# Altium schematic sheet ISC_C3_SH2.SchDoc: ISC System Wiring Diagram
size C; DrawnBy: Filiberto Clara; Engineer: Filiberto Clara; Organization: LIGO Laboratory; Address1: California Institute of Technology; Address2: Massachusetts Institute of Technology; SheetNumber: 6; SheetTotal: 37
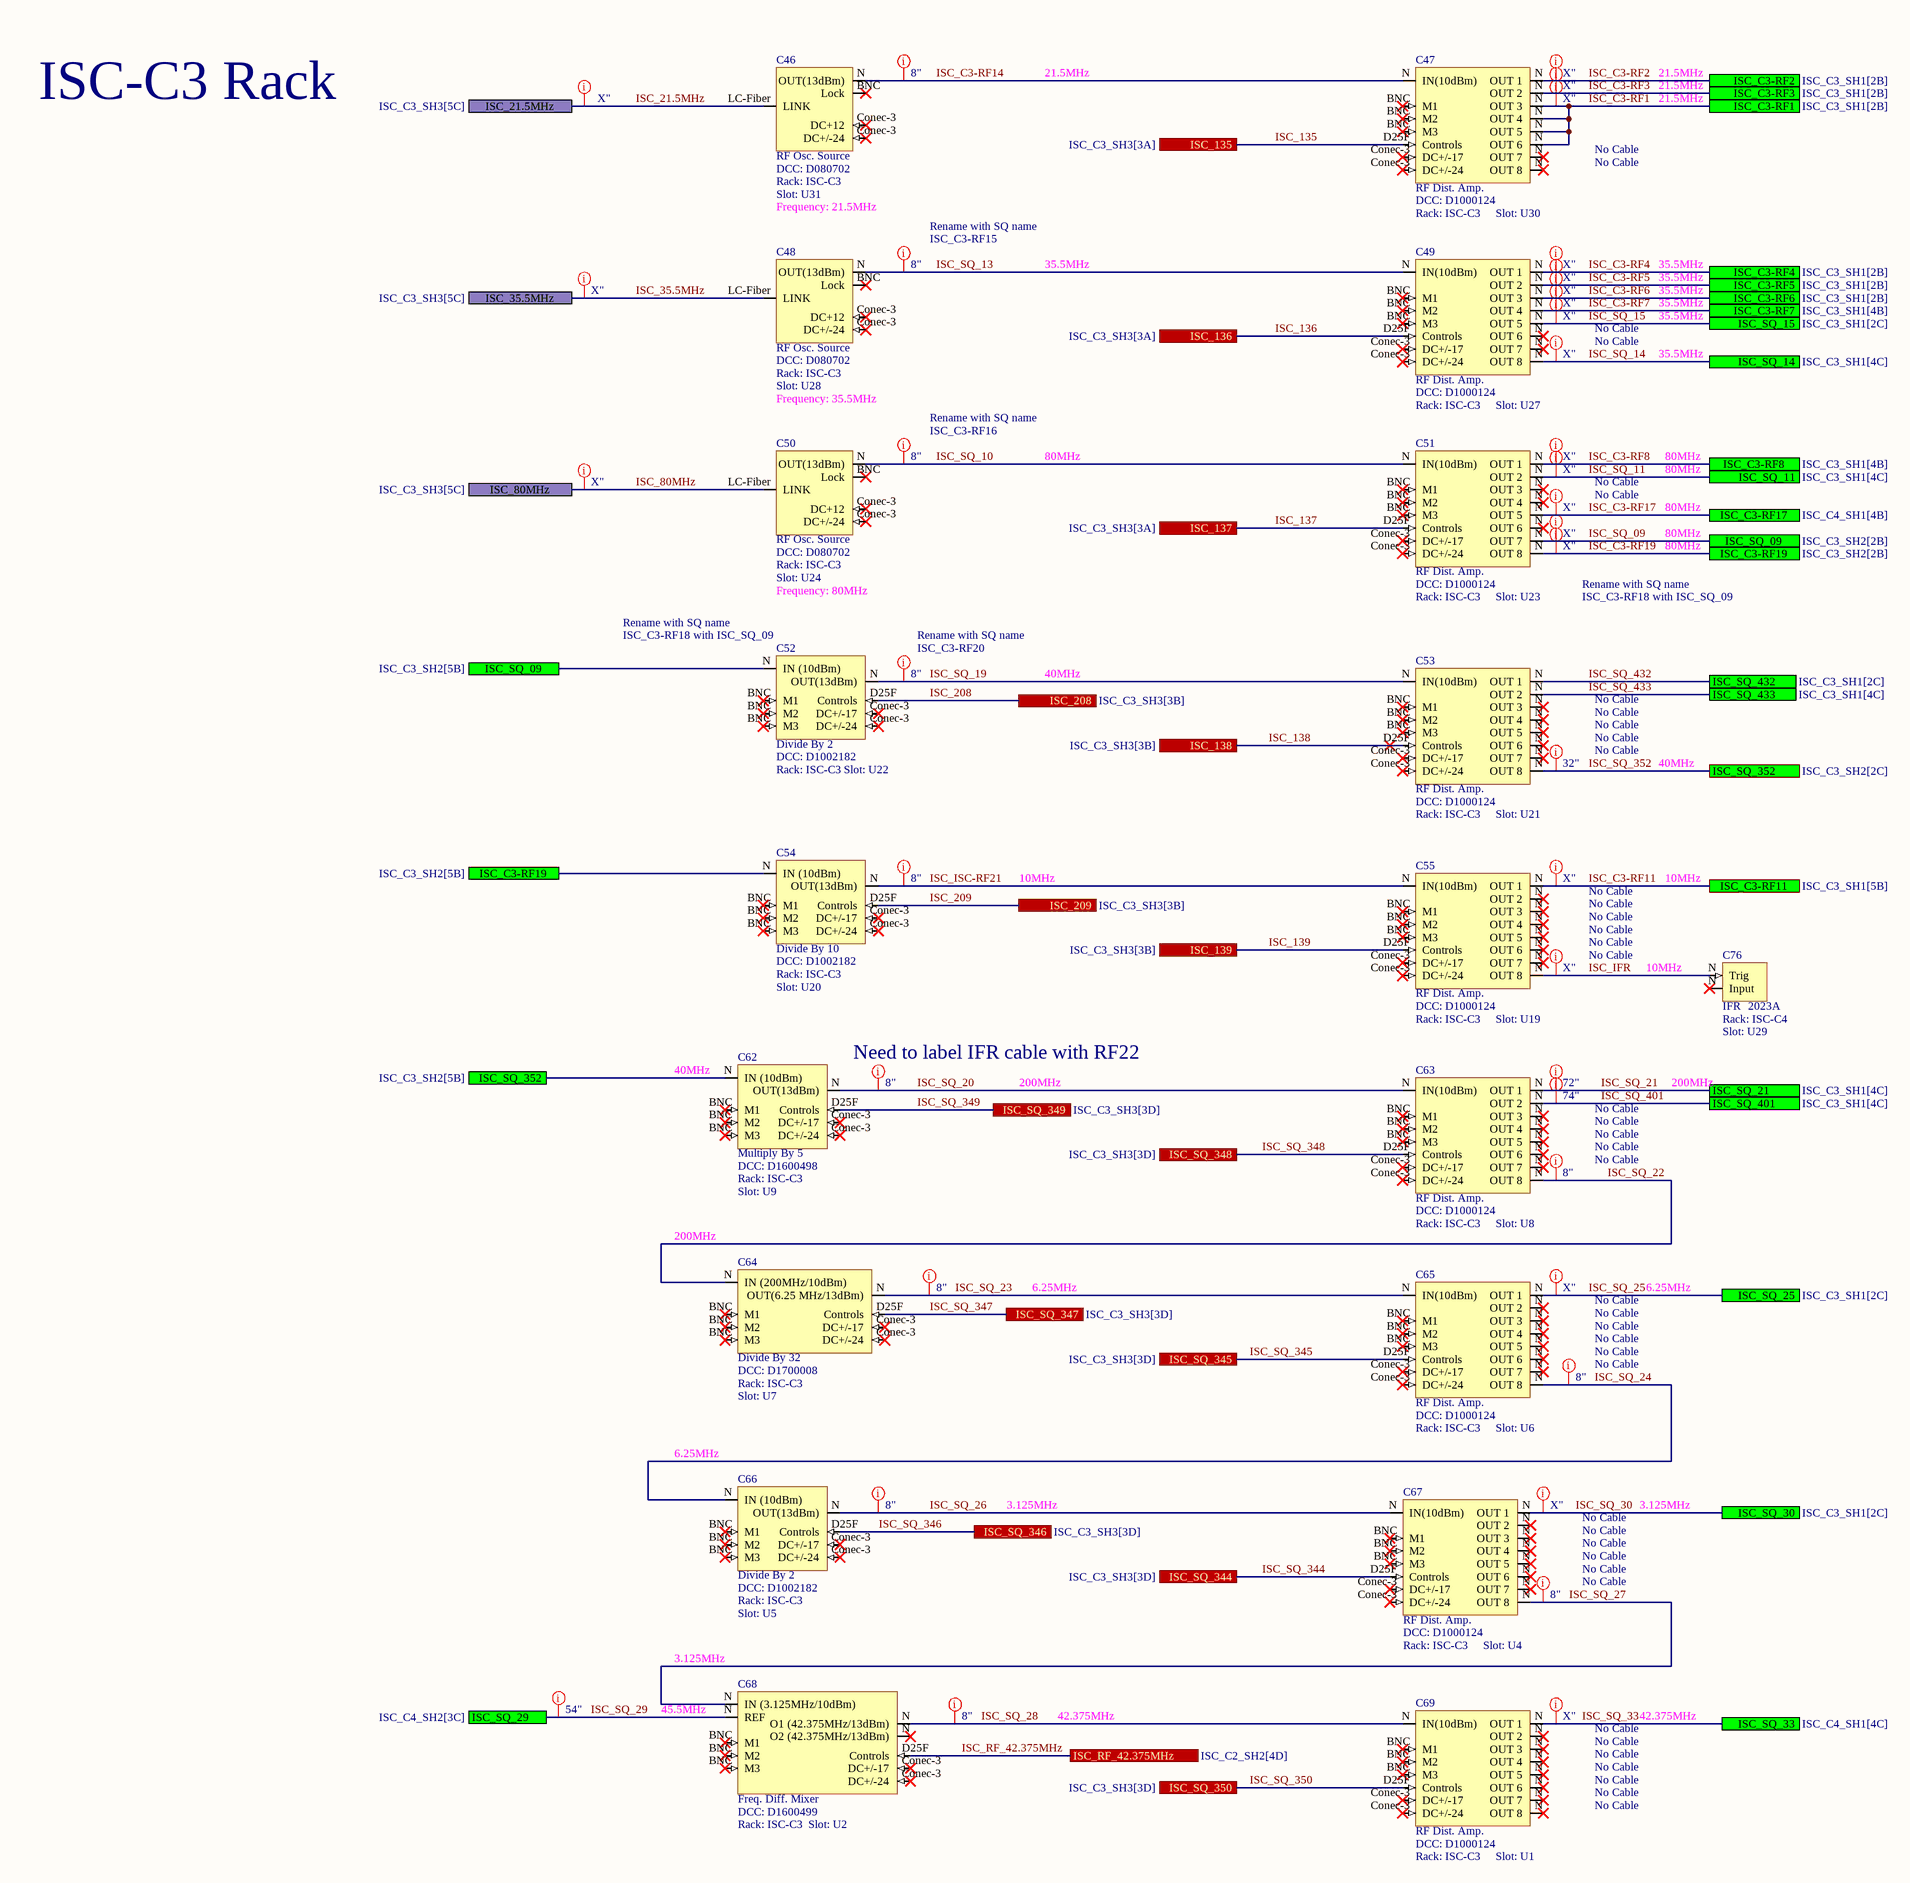
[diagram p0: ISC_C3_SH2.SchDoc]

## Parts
C46  RF Osc. Source  DCC: D080702  Rack: ISC-C3  Slot: U31  Frequency: 21.5MHz
C47  RF Dist. Amp.  DCC: D1000124  Rack: ISC-C3  Slot: U30
C48  RF Osc. Source  DCC: D080702  Rack: ISC-C3  Slot: U28  Frequency: 35.5MHz
C49  RF Dist. Amp.  DCC: D1000124  Rack: ISC-C3  Slot: U27
C50  RF Osc. Source  DCC: D080702  Rack: ISC-C3  Slot: U24  Frequency: 80MHz
C51  RF Dist. Amp.  DCC: D1000124  Rack: ISC-C3  Slot: U23
C52  Divide By 2  DCC: D1002182  Rack: ISC-C3  Slot: U22
C53  RF Dist. Amp.  DCC: D1000124  Rack: ISC-C3  Slot: U21
C54  Divide By 10  DCC: D1002182  Rack: ISC-C3  Slot: U20
C55  RF Dist. Amp.  DCC: D1000124  Rack: ISC-C3  Slot: U19
C62  Multiply By 5  DCC: D1600498  Rack: ISC-C3  Slot: U9
C63  RF Dist. Amp.  DCC: D1000124  Rack: ISC-C3  Slot: U8
C64  Divide By 32  DCC: D1700008  Rack: ISC-C3  Slot: U7
C65  RF Dist. Amp.  DCC: D1000124  Rack: ISC-C3  Slot: U6
C66  Divide By 2  DCC: D1002182  Rack: ISC-C3  Slot: U5
C67  RF Dist. Amp.  DCC: D1000124  Rack: ISC-C3  Slot: U4
C68  Freq. Diff. Mixer  DCC: D1600499  Rack: ISC-C3  Slot: U2
C69  RF Dist. Amp.  DCC: D1000124  Rack: ISC-C3  Slot: U1
C76  2023A  Rack: ISC-C4  Slot: U29

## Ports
ISC_21.5MHz (see ISC_C3_SH3[5C]), ISC_35.5MHz (see ISC_C3_SH3[5C]), ISC_80MHz (see ISC_C3_SH3[5C]), ISC_135 (see ISC_C3_SH3[3A]), ISC_136 (see ISC_C3_SH3[3A]), ISC_137 (see ISC_C3_SH3[3A]), ISC_138 (see ISC_C3_SH3[3B]), ISC_139 (see ISC_C3_SH3[3B]), ISC_208 (see ISC_C3_SH3[3B]), ISC_209 (see ISC_C3_SH3[3B]), ISC_C3-RF1 (see ISC_C3_SH1[2B]), ISC_C3-RF2 (see ISC_C3_SH1[2B]), ISC_C3-RF3 (see ISC_C3_SH1[2B]), ISC_C3-RF4 (see ISC_C3_SH1[2B]), ISC_C3-RF5 (see ISC_C3_SH1[2B]), ISC_C3-RF6 (see ISC_C3_SH1[2B]), ISC_C3-RF7 (see ISC_C3_SH1[4B]), ISC_C3-RF8 (see ISC_C3_SH1[4B]), ISC_C3-RF11 (see ISC_C3_SH1[5B]), ISC_C3-RF17 (see ISC_C4_SH1[4B]), ISC_C3-RF19 (see ISC_C3_SH2[2B]), ISC_C3-RF19 (see ISC_C3_SH2[5B]), ISC_RF_42.375MHz (see ISC_C2_SH2[4D]), ISC_SQ_09 (see ISC_C3_SH2[2B]), ISC_SQ_09 (see ISC_C3_SH2[5B]), ISC_SQ_11 (see ISC_C3_SH1[4C]), ISC_SQ_14 (see ISC_C3_SH1[4C]), ISC_SQ_15 (see ISC_C3_SH1[2C]), ISC_SQ_21 (see ISC_C3_SH1[4C]), ISC_SQ_25 (see ISC_C3_SH1[2C]), ISC_SQ_29 (see ISC_C4_SH2[3C]), ISC_SQ_30 (see ISC_C3_SH1[2C]), ISC_SQ_33 (see ISC_C4_SH1[4C]), ISC_SQ_344 (see ISC_C3_SH3[3D]), ISC_SQ_345 (see ISC_C3_SH3[3D]), ISC_SQ_346 (see ISC_C3_SH3[3D]), ISC_SQ_347 (see ISC_C3_SH3[3D]), ISC_SQ_348 (see ISC_C3_SH3[3D]), ISC_SQ_349 (see ISC_C3_SH3[3D]), ISC_SQ_350 (see ISC_C3_SH3[3D]), ISC_SQ_352 (see ISC_C3_SH2[2C]), ISC_SQ_352 (see ISC_C3_SH2[5B]), ISC_SQ_401 (see ISC_C3_SH1[4C]), ISC_SQ_432 (see ISC_C3_SH1[2C]), ISC_SQ_433 (see ISC_C3_SH1[4C])

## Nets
ISC_21.5MHz: C46.LC-Fiber(LINK) ; port ISC_21.5MHz
ISC_35.5MHz: C48.LC-Fiber(LINK) ; port ISC_35.5MHz
ISC_80MHz: C50.LC-Fiber(LINK) ; port ISC_80MHz
ISC_135: C47.D25F(Controls) ; port ISC_135
ISC_136: C49.D25F(Controls) ; port ISC_136
ISC_137: C51.D25F(Controls) ; port ISC_137
ISC_138: C53.D25F(Controls) ; port ISC_138
ISC_139: C55.D25F(Controls) ; port ISC_139
ISC_208: C52.D25F(Controls) ; port ISC_208
ISC_209: C54.D25F(Controls) ; port ISC_209
ISC_C3-RF1: C47.N(OUT_3) ; port ISC_C3-RF1
ISC_C3-RF2: C47.N(OUT_1) ; port ISC_C3-RF2
ISC_C3-RF3: C47.N(OUT_2) ; port ISC_C3-RF3
ISC_C3-RF4: C49.N(OUT_1) ; port ISC_C3-RF4
ISC_C3-RF5: C49.N(OUT_2) ; port ISC_C3-RF5
ISC_C3-RF6: C49.N(OUT_3) ; port ISC_C3-RF6
ISC_C3-RF7: C49.N(OUT_4) ; port ISC_C3-RF7
ISC_C3-RF8: C51.N(OUT_1) ; port ISC_C3-RF8
ISC_C3-RF11: C55.N(OUT_1) ; port ISC_C3-RF11
ISC_C3-RF14: C46.N(OUT(13dBm)) C47.N(IN(10dBm))
ISC_C3-RF17: C51.N(OUT_5) ; port ISC_C3-RF17
ISC_C3-RF19: C51.N(OUT_8) C54.N(IN_(10dBm)) ; port ISC_C3-RF19
ISC_IFR: C55.N(OUT_8) C76.N(Input)
ISC_ISC-RF21: C54.N(OUT(13dBm)) C55.N(IN(10dBm))
ISC_RF_42.375MHz: C68.D25F(Controls) ; port ISC_RF_42.375MHz
ISC_SQ_09: C51.N(OUT_7) C52.N(IN_(10dBm)) ; port ISC_SQ_09
ISC_SQ_10: C50.N(OUT(13dBm)) C51.N(IN(10dBm))
ISC_SQ_11: C51.N(OUT_2) ; port ISC_SQ_11
ISC_SQ_13: C48.N(OUT(13dBm)) C49.N(IN(10dBm))
ISC_SQ_14: C49.N(OUT_8) ; port ISC_SQ_14
ISC_SQ_15: C49.N(OUT_5) ; port ISC_SQ_15
ISC_SQ_19: C52.N(OUT(13dBm)) C53.N(IN(10dBm))
ISC_SQ_20: C62.N(OUT(13dBm)) C63.N(IN(10dBm))
ISC_SQ_21: C63.N(OUT_1) ; port ISC_SQ_21
ISC_SQ_22: C63.N(OUT_8) C64.N(IN_(200MHz/10dBm))
ISC_SQ_23: C64.N(OUT(6.25_MHz/13dBm)) C65.N(IN(10dBm))
ISC_SQ_24: C65.N(OUT_8) C66.N(IN_(10dBm))
ISC_SQ_25: C65.N(OUT_1) ; port ISC_SQ_25
ISC_SQ_26: C66.N(OUT(13dBm)) C67.N(IN(10dBm))
ISC_SQ_27: C67.N(OUT_8) C68.N(IN_(3.125MHz/10dBm))
ISC_SQ_28: C68.N(O1_(42.375MHz/13dBm)) C69.N(IN(10dBm))
ISC_SQ_29: C68.N(REF) ; port ISC_SQ_29
ISC_SQ_30: C67.N(OUT_1) ; port ISC_SQ_30
ISC_SQ_33: C69.N(OUT_1) ; port ISC_SQ_33
ISC_SQ_344: C67.D25F(Controls) ; port ISC_SQ_344
ISC_SQ_345: C65.D25F(Controls) ; port ISC_SQ_345
ISC_SQ_346: C66.D25F(Controls) ; port ISC_SQ_346
ISC_SQ_347: C64.D25F(Controls) ; port ISC_SQ_347
ISC_SQ_348: C63.D25F(Controls) ; port ISC_SQ_348
ISC_SQ_349: C62.D25F(Controls) ; port ISC_SQ_349
ISC_SQ_350: C69.D25F(Controls) ; port ISC_SQ_350
ISC_SQ_352: C53.N(OUT_8) C62.N(IN_(10dBm)) ; port ISC_SQ_352
ISC_SQ_401: C63.N(OUT_2) ; port ISC_SQ_401
ISC_SQ_432: C53.N(OUT_1) ; port ISC_SQ_432
ISC_SQ_433: C53.N(OUT_2) ; port ISC_SQ_433

Not connected (* = marked no-connect by the designer): C46 BNC(Lock)* Conec-3(DC+12)*; C47 BNC(M1)* Conec-3(DC+/-17)*; C48 BNC(Lock)* Conec-3(DC+12)*; C49 BNC(M1)* Conec-3(DC+/-17)*; C50 BNC(Lock)* Conec-3(DC+12)*; C51 BNC(M1)* Conec-3(DC+/-17)*; C52 BNC(M1)* Conec-3(DC+/-17)*; C53 BNC(M1)* Conec-3(DC+/-17)*; C54 BNC(M1)* Conec-3(DC+/-17)*; C55 BNC(M1)* Conec-3(DC+/-17)*; C62 BNC(M1)* Conec-3(DC+/-17)*; C63 BNC(M1)* Conec-3(DC+/-17)*; C64 BNC(M1)* Conec-3(DC+/-17)*; C65 BNC(M1)* Conec-3(DC+/-17)*; C66 BNC(M1)* Conec-3(DC+/-17)*; C67 BNC(M1)* Conec-3(DC+/-17)*; C68 BNC(M1)* Conec-3(DC+/-17)*; C69 BNC(M1)* Conec-3(DC+/-17)*

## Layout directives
Length: 8": ISC_C3-RF14, ISC_ISC-RF21, ISC_SQ_10, ISC_SQ_13, ISC_SQ_19, ISC_SQ_20, ISC_SQ_22, ISC_SQ_23, ISC_SQ_24, ISC_SQ_26, ISC_SQ_27, ISC_SQ_28
Length: 32": ISC_SQ_352
Length: 72": ISC_SQ_21
Length: X": ISC_21.5MHz, ISC_35.5MHz, ISC_80MHz, ISC_C3-RF1, ISC_C3-RF2, ISC_C3-RF3, ISC_C3-RF4, ISC_C3-RF5, ISC_C3-RF6, ISC_C3-RF7, ISC_C3-RF8, ISC_C3-RF11, ISC_C3-RF17, ISC_C3-RF19, ISC_IFR, ISC_SQ_09, ISC_SQ_11, ISC_SQ_14, ISC_SQ_15, ISC_SQ_25, ISC_SQ_30, ISC_SQ_33
Length: 54": ISC_SQ_29
Length: 74": ISC_SQ_401

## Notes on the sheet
- ISC-C3 Rack
- 21.5MHz
- No Cable
- ISC_C3-RF15
- Rename with SQ name
- 35.5MHz
- ISC_C3-RF16
- 80MHz
- ISC_C3-RF18 with ISC_SQ_09
- (near C52) ISC_C3-RF18 with ISC_SQ_09
- ISC_C3-RF20
- 40MHz
- 10MHz
- (near C76) 10MHz
- (near C62) 40MHz
- (near C62) Need to label IFR cable with RF22
- 200MHz
- (near C64) 200MHz
- 6.25MHz
- (near C66) 6.25MHz
- 3.125MHz
- (near C68) 3.125MHz
- (near C68) 45.5MHz
- 42.375MHz

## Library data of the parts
C46 C48 C50 = RF Osc. Source: Serial: Sxxxxxxx; System: ISC
C47 C49 C51 = RF Distribution Amplifier: Serial: Sxxxxxxx; System: ISC
C52 = Divide By 2: Serial: Sxxxxxxx; System: ISC; Frequency: 40MHz
C53 C55 C63 C65 C67 = RF Distribution Amplifier: Serial: Sxxxxxxx; System: ISC; Frequency: 6.25MHz
C54 = Divide By 10: Serial: Sxxxxxxx; System: ISC; Frequency: 3.125MHz
C62 = Divide By 2: Divide By 5; Serial: Sxxxxxxx; System: ISC; Frequency: 3.125MHz
C64 = Divide By 32: Serial: Sxxxxxxx; System: ISC; Frequency: 6.25MHz
C66 = Divide By 2: Serial: Sxxxxxxx; System: ISC; Frequency: 3.125MHz
C68 = Freq. Diff. Mixer: Serial: Sxxxxxxx; System: ISC; Frequency: 42.375MHz
C69 = RF Distribution Amplifier: Serial: Sxxxxxxx; System: ISC; Frequency: 42.375MHz
C76 = Aeroflex: IFR; Serial: Sxxxxxxx; System: ISC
